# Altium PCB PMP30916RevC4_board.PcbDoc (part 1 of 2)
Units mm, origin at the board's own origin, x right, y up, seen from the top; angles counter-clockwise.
Board outline 58.42 x 31.75 mm, 4 copper layers (Top Layer, Layer 2, Layer 3, Bottom Layer), stack 1.787 mm thick; 61 components, 27 nets, 160 pads, 105 vias.
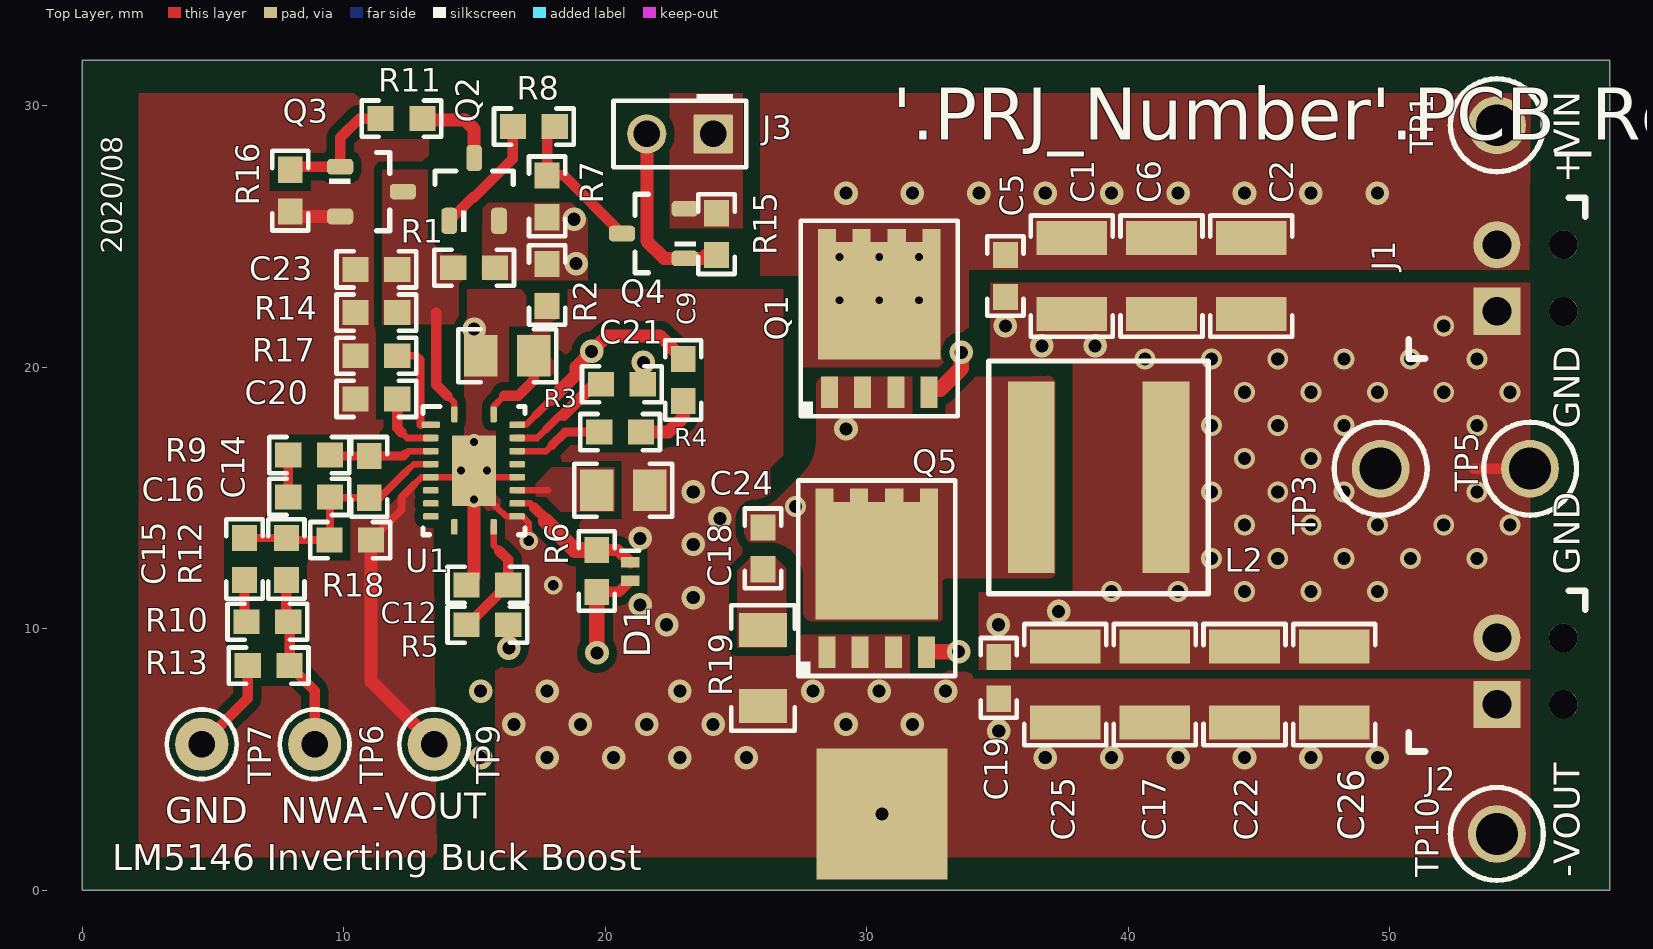
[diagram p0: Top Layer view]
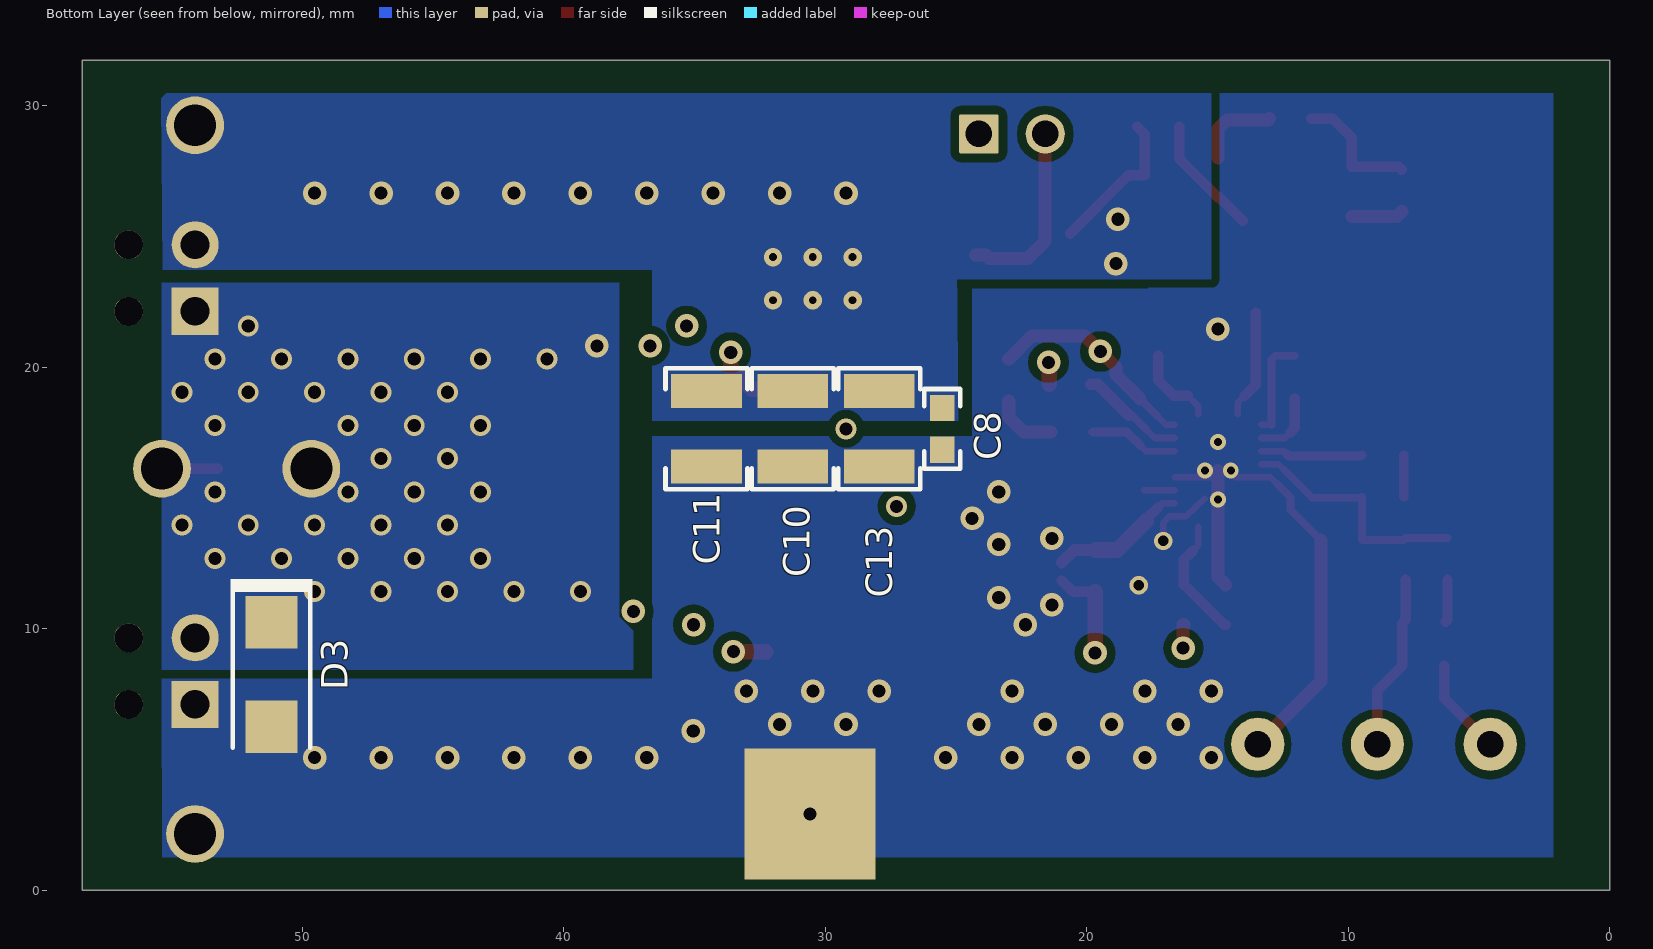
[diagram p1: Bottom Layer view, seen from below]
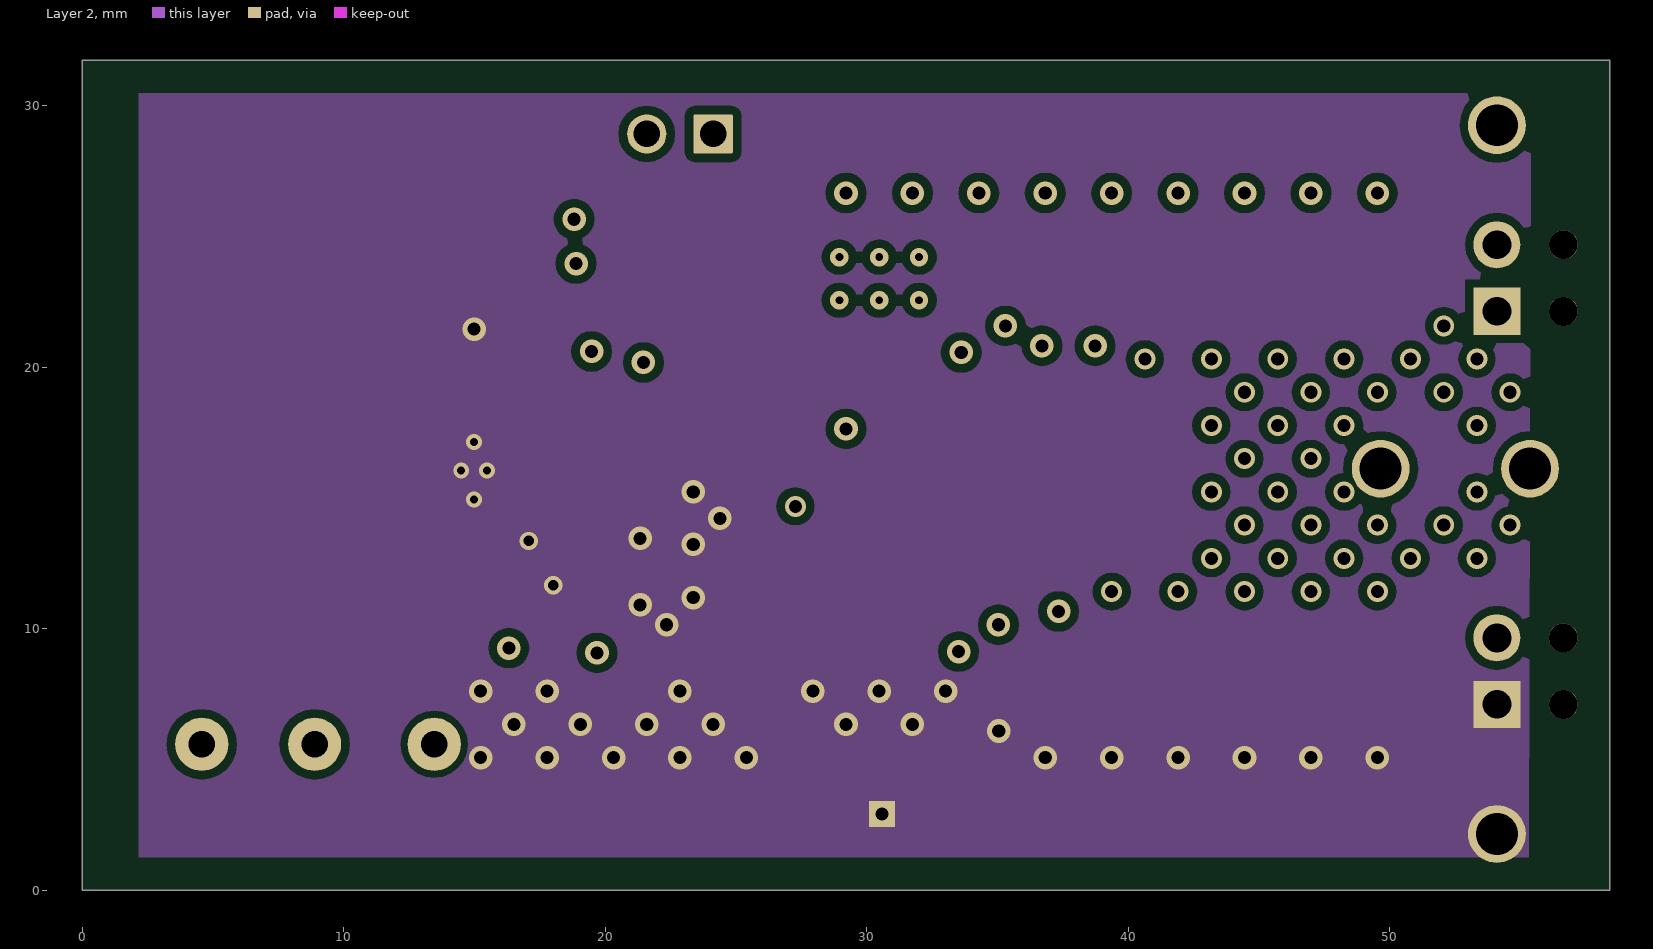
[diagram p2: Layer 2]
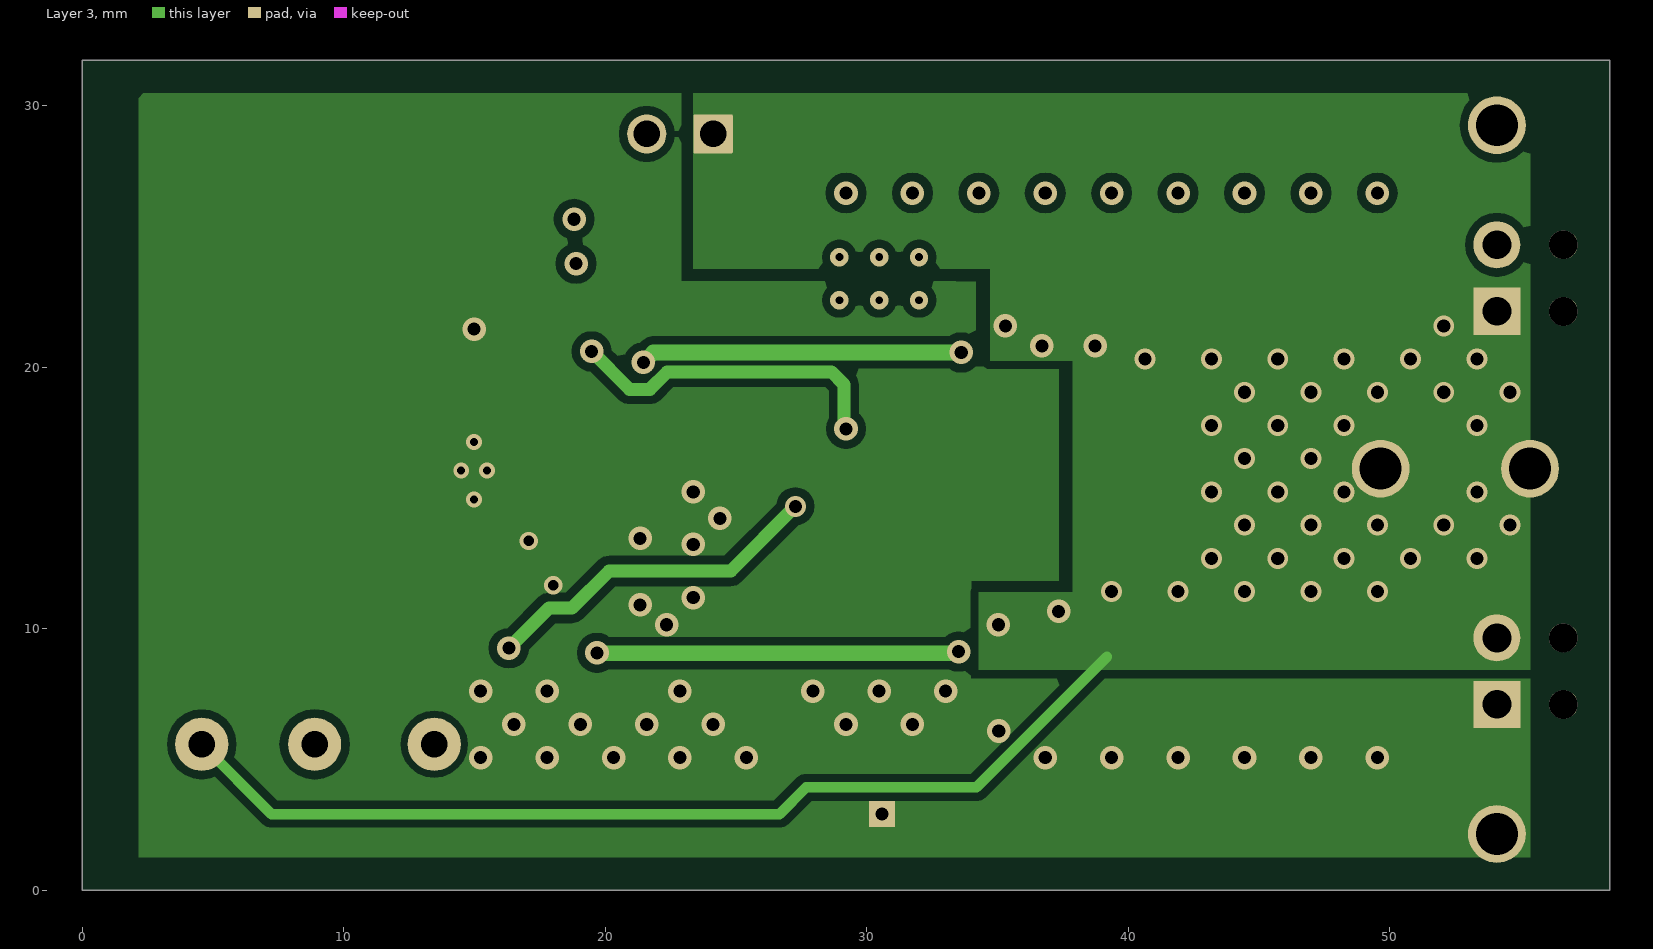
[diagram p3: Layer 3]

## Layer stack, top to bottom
Top Solder: solder mask 0.0102, Solder Resist, Dk 3.5
Top Layer: signal copper 0.0356
Dielectric 1: prepreg 0.0711, PP-006, Dk 4.1
Layer 2: signal copper 0.035
Dielectric1: core 1.5037, FR-4, Dk 4.8
Layer 3: signal copper 0.035
Dielectric 2: prepreg 0.0711, PP-006, Dk 4.1
Bottom Layer: signal copper 0.0356
Bottom Solder: solder mask 0.0102, Solder Resist, Dk 3.5

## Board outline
0,0 0,31.75 58.42,31.75 58.42,0

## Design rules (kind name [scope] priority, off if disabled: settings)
AcuteAngle [All] p1: minimum=4.50000000000000E+0001 checktracksonly=FALSE
AssemblyTestPointUsage [All] p1: valid=2
BoardOutlineClearance BoardOutlineClearance_MountingHoles [OnCopper and InComponentClass('Mounting Holes')] p1: gap=1 ignorepadtopadclearanceinfootprint=FALSE
BoardOutlineClearance BoardOutlineClearance_Poly [OnCopper and IsPoly] p2: gap=0.635 ignorepadtopadclearanceinfootprint=FALSE
BoardOutlineClearance [OnCopper and Not InComponentClass('Logo') and not InComponentClass('FiducialMark') and not InRegion(1000,500,4000,800) and not InPoly] p3: gap=1.905 ignorepadtopadclearanceinfootprint=FALSE
Clearance Clearance_Keepouts [((IsTrack Or IsArc) And Not InPoly) And IsFree and IsKeepOut vs ((IsTrack Or IsArc) And Not InPoly) And IsFree and IsKeepOut] p1: gap=0 ignorepadtopadclearanceinfootprint=FALSE
Clearance clearance_poly-VOUT [InPolygon and InNet('NetC10_2') vs InNet('NetC10_2')] p2: gap=0.2 ignorepadtopadclearanceinfootprint=TRUE
Clearance clearance_poly_VCC [InPolygon and InNet('NetC24_1')] p3: gap=0.2 ignorepadtopadclearanceinfootprint=TRUE
Clearance Clearance_Poly [InPolygon] p4: gap=0.32 ignorepadtopadclearanceinfootprint=TRUE
Clearance Clearance_FiducialMark [IsKeepOut and InComponentClass('FiducialMark') vs IsPad and InComponentClass('FiducialMark')] p5: gap=0 ignorepadtopadclearanceinfootprint=FALSE
Clearance [All] p6: gap=0.2 ignorepadtopadclearanceinfootprint=TRUE
ComponentClearance ComponentClearance_MountingHoles_FiducialMarks [InComponentClass('Mounting Holes') vs InComponentClass('FiducialMark')] p1: gap=1.27 collisioncheckmode=3 verticalgap=0.254 showdistances=FALSE
ComponentClearance ComponentClearance_Shunt [InComponentClass('Header') vs InComponentClass('Shunt')] p2: gap=0 collisioncheckmode=3 verticalgap=0 showdistances=FALSE
ComponentClearance ComponentClearance_Logo [InComponentClass('Logo')] p3: gap=1.27 collisioncheckmode=3 verticalgap=0.254 showdistances=FALSE
ComponentClearance ComponentClearance_ScrewToNut [(HasFootprint('NY PMS 440 0025 PH')) vs (HasFootprint('Keystone_1902C'))] p4: gap=0.127 collisioncheckmode=3 verticalgap=0.254 showdistances=FALSE
ComponentClearance ComponentClearance_MountingHoles [InComponentClass('Mounting Holes')] p5: gap=6.35 collisioncheckmode=3 verticalgap=2540 showdistances=FALSE
ComponentClearance ComponentClearance_SmallPassives [HasFootprint('0201*') or HasFootprint('0402*') or HasFootprint('0508') or HasFootprint('0603*') or HasFootprint('0612') or HasFootprint('0805*') or HasFootprint('0815*') or HasFootprint('0830*') or HasFootprint('1206*') or HasFootprint('1210*') or HasFootprint('1808*') or HasFootprint('1812*') or HasFootprint('1825*') or HasFootprint('2010*') or HasFootprint('2220*') or HasFootprint('2225*') or HasFootprint('2512*') or HasFootprint('2728*') or HasFootprint('3518*') or HasFootprint('X1-DFN1006-2') vs HasFootprint('0201*') or HasFootprint('0402*') or HasFootprint('0508') or HasFootprint('0603*') or HasFootprint('0612') or HasFootprint('0805*') or HasFootprint('0815*') or HasFootprint('0830*') or HasFootprint('1206*') or HasFootprint('1210*') or HasFootprint('1808*') or HasFootprint('1812*') or HasFootprint('1825*') or HasFootprint('2010*') or HasFootprint('2220*') or HasFootprint('2225*') or HasFootprint('2512*') or HasFootprint('2728*') or HasFootprint('3518*') or HasFootprint('X1-DFN1006-2')] p6: gap=0.38 collisioncheckmode=3 verticalgap=0.254 showdistances=FALSE
ComponentClearance ComponentClearance_THtoSMT [IsThruComponent vs IsSMTComponent] p7: gap=1.016 collisioncheckmode=3 verticalgap=0.762 showdistances=FALSE
ComponentClearance ComponentClearance_THtoTH [IsThruComponent vs IsThruComponent] p8: gap=0.762 collisioncheckmode=3 verticalgap=0.762 showdistances=FALSE
ComponentClearance [All] p9: gap=0.762 collisioncheckmode=3 verticalgap=0.254 showdistances=FALSE
DiffPairsRouting [All] p1: maxlimit=2.54 minlimit=0.254 mostfreqgap=0.254 toplayer_minwidth=0.381 toplayer_maxwidth=0.381 toplayer_prefwidth=0.381 midlayer1_minwidth=0.381 midlayer1_maxwidth=0.381 midlayer1_prefwidth=0.381 midlayer2_minwidth=0.381 midlayer2_maxwidth=0.381 midlayer2_prefwidth=0.381 bottomlayer_minwidth=0.381 bottomlayer_maxwidth=0.381 bottomlayer_prefwidth=0.381 maxuncoupledlength=25.4
FabricationTestPointUsage TestPointUsage [All] p1: valid=2 allowmultiple=FALSE
FabricationTestpoint Testpoint [All] p1: side=3 testpointundercomponent=TRUE minsize=1.016 maxsize=2.54 preferedsize=1.524 minholesize=0 maxholesize=1.016 preferedholesize=0.813 testpointgrid=0.025 allowsidetop=TRUE allowsidebottom=TRUE usegrid=TRUE gridtolerance=0
FanoutControl Fanout_LCC [IsLCC] p1: bgadir=Out bgaviamode=Centered fanoutstyle=Auto fanoutdirection=Alternating viagrid=0.025 // Fanout_LCC (Default Rule)
FanoutControl Fanout_BGA [IsBGA] p2: bgadir=Out bgaviamode=Centered fanoutstyle=Auto fanoutdirection=Alternating viagrid=0.025 // Fanout_BGA (Default Rule)
FanoutControl Fanout_Default [All] p4: bgadir=Out bgaviamode=Centered fanoutstyle=Auto fanoutdirection=Alternating viagrid=0.025 // Fanout_Default (Default Rule)
FanoutControl Fanout_Small [(CompPinCount < 5)] p5: bgadir=Out bgaviamode=Centered fanoutstyle=Auto fanoutdirection=OutThenIn viagrid=0.025 // Fanout_Small (Default Rule)
HoleSize [All] p1: absolutevalues=TRUE maxlimit=6.375 minlimit=0.3 maxpercent=80.000 minpercent=20.000
MinimumAnnularRing MinimumAnnularRing_ThermalPadVias [IsVia and InAnyComponent] p1: minimumring=0.15
MinimumAnnularRing [All] p2: minimumring=0.2
MinimumSolderMaskSliver MinimumSolderMaskSliver_Logo [InComponentClass('Logo') vs InComponentClass('Logo')] p1: minsoldermaskwidth=0.018
MinimumSolderMaskSliver [All] p2: minsoldermaskwidth=0.1
PlaneConnect [All] p1: planeconnectstyle=Relief reliefexpansion=0.254 reliefentries=4 reliefconductorwidth=0.254 reliefairgap=0.254
PolygonConnect PolygonConnect_TP9 [All vs InComponent('TP9')] p1: thpad.connectstyle=NoConnect thpad.reliefconductorwidth=0.254 thpad.reliefentries=4 thpad.polygonreliefangle="90 Angle" thpad.airgapwidth=0.254 smdpad.connectstyle=Relief smdpad.reliefconductorwidth=0.254 smdpad.reliefentries=4 smdpad.polygonreliefangle="90 Angle" smdpad.airgapwidth=0.254 via.connectstyle=Relief via.reliefconductorwidth=0.254 via.reliefentries=4 via.polygonreliefangle="90 Angle" via.airgapwidth=0.254
PolygonConnect PolygonConnect_TP7 [All vs InComponent('TP7')] p2: thpad.connectstyle=NoConnect thpad.reliefconductorwidth=0.254 thpad.reliefentries=4 thpad.polygonreliefangle="90 Angle" thpad.airgapwidth=0.254 smdpad.connectstyle=Direct smdpad.reliefconductorwidth=0.254 smdpad.reliefentries=4 smdpad.polygonreliefangle="90 Angle" smdpad.airgapwidth=0.254 via.connectstyle=Direct via.reliefconductorwidth=0.254 via.reliefentries=4 via.polygonreliefangle="90 Angle" via.airgapwidth=0.254
PolygonConnect [All] p3: connectstyle=Direct reliefconductorwidth=0.254 reliefentries=4 polygonreliefangle="90 Angle" airgapwidth=0.254
RoutingVias ThermalPadVias [IsVia and InAnyComponent] p1: holewidth=0.2 width=0.5 viastyle="Through Hole" minholewidth=0.2 minwidth=0.5 maxholewidth=0.33 maxwidth=0.6
RoutingVias [All] p2: holewidth=0.5 width=0.9 viastyle="Through Hole" minholewidth=0.3 minwidth=0.6 maxholewidth=1.016 maxwidth=1.651
SilkToBoardRegionClearance [Not ((IsComment or IsDesignator) And (Hide <> 'False')) and not InRegion(1000,500,4000,800)] p1:
SilkToSilkClearance SilkToSilkClearance_Pb-FreeLogo [(HasFootprint('Pb-Free_Overlay_Medium') OR HasFootprint('Pb-Free_Overlay_Small')) vs (HasFootprint('Pb-Free_Overlay_Medium') OR HasFootprint('Pb-Free_Overlay_Small'))] p1: silktosilkclearance=0
SilkToSilkClearance [All] p2: silktosilkclearance=0.1
SilkToSolderMaskClearance SilkToComponentPadClearance [(IsPad or IsFill or IsRegion) and InAnycomponent] p1: minsilkscreentomaskgap=0.127 clearancetoexposedcopper=TRUE
SilkToSolderMaskClearance "Silk to Solder Mask Opening" [All] p2: minsilkscreentomaskgap=0.1 clearancetoexposedcopper=FALSE
SolderMaskExpansion [All] p1: expansion=0.05 istentingtop=FALSE
UnRoutedNet [All] p1: checkbadconnections=TRUE
Width [All] p1: maxlimit=2.54 minlimit=0.152 preferedwidth=0.254 checkconnectedcopper=TRUE
14 further rules are at their usual default settings.

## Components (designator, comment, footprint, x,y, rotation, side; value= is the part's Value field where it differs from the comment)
C1 "GRM32ER72A225KA35L" 1210_270 37.846,23.495 r270 top value=2.2uF
C2 "GRM32ER72A225KA35L" 1210_270 44.704,23.495 r270 top value=2.2uF
C5 "GRM188R72A104KA35D" 0603 35.306,23.495 r270 top value=0.1uF
C6 "GRM32ER72A225KA35L" 1210_270 41.275,23.495 r270 top value=2.2uF
C8 "GRM188R72A104KA35D" 0603 25.527,17.653 r270 bottom value=0.1uF
C9 "GRM188R71E104KA01D" 0603 22.987,19.52 r90 top value=0.1uF
C10 "GRM32ER72A225KA35L" 1210_270 31.242,17.653 r270 bottom value=2.2uF
C11 "GRM32ER72A225KA35L" 1210_270 34.544,17.653 r270 bottom value=2.2uF
C12 "GRM1885C1H270JA01D" 0603 15.494,11.684 r180 top value=27pF
C13 "GRM32ER72A225KA35L" 1210_270 27.94,17.653 r270 bottom value=2.2uF
C14 "GRM188R71H471KA01D" 0603 10.976,15.815 r270 top value=470pF
C15 "GRM188R71H102KA01D" 0603 6.208,12.676 r90 top value=1000pF
C16 "GRM188R71H103KA01D" 0603 8.683,15.051 r0 top value=0.01uF
C17 "GRM32ER71E226KE15L" 1210_270 41.021,7.874 r90 top value=22uF
C18 "C1608X7R2A102K080AA" 0603 26.035,13.081 r270 top value=1000pF
C19 "GRM188R71E104KA01D" 0603 35.052,8.128 r270 top value=0.1uF
C20 "GRM188R71C683KA01D" 0603 11.246,18.796 r180 top value=0.068uF
C21 "GRM21BR72A474KA73L" 0805_HV 16.256,20.447 r180 top value=0.47uF
C22 "GRM32ER71E226KE15L" 1210_270 44.45,7.874 r90 top value=22uF
C23 "GRM1885C1H101JA01D" 0603 11.246,23.749 r180 top value=100pF
C24 "GCM21BR71E225KA73L" 0805_HV 20.691,15.306 r0 top value=2.2uF
C25 "GRM32ER71E226KE15L" 1210_270 37.592,7.874 r90 top value=22uF
C26 "GRM32ER71E226KE15L" 1210_270 47.879,7.874 r90 top value=22uF
D1 "BAT54LP-7" X1-DFN1006-2 20.955,12.192 r270 top value=30V
D3 "B2100A-13-F" SMA 51.181,8.255 r270 bottom value=100V
J1 "1725656" CONN_1725656 54.102,23.419 r90 top
J2 "1725656" CONN_1725656 54.102,8.387 r90 top
J3 "PEC02SAAN" CONN_PEC02SAAN 22.86,28.93 r180 top
L2 "XAL8080-223MEB" XAL8080 38.867,15.799 r0 top value=22uH
Q1 "BSC117N08NS5ATMA1" PG-TDSON-8 30.48,21.875 r90 top value=80V
Q2 "BSS63" SOT-23 14.989,26.807 r90 top value="100 V"
Q3 "BSS123" SOT-23 11.066,26.725 r0 top value=100V
Q4 "BSS123" SOT-23 21.844,25.12 r180 top value=100V
Q5 "BSC117N08NS5ATMA1" PG-TDSON-8 30.385,11.938 r90 top value=80V
R1 "CRCW0603200KFKEA" 0603 14.989,23.81 r0 top value=200k
R2 "RMCF0603ZT0R00" 0603 17.78,23.152 r90 top value=0
R3 "CRCW06034R75FKEA" 0603 20.636,19.357 r0 top value=4.75
R4 "RMCF0603ZT0R00" 0603 20.574,17.526 r0 top value=0
R5 "CRCW0603215RFKEA" 0603 15.494,10.16 r0 top value=215
R6 "RMCF0603ZT0R00" 0603 19.675,12.216 r270 top value=0
R7 "CRCW0603100KFKEA" 0603 17.78,26.543 r270 top value=100k
R8 "CRCW060349K9FKEA" 0603 17.272,29.21 r180 top value=49.9k
R9 "CRCW06034K99FKEA" 0603 8.683,16.648 r0 top value=4.99k
R10 "CRCW06032K67FKEA" 0603 7.083,10.273 r0 top value=2.67k
R11 "CRCW0603100KFKEA" 0603 12.209,29.519 r0 top value=100k
R12 "CRCW060349K9FKEA" 0603 7.808,12.676 r270 top value=49.9k
R13 "RC0603FR-0749R9L" 0603 7.133,8.598 r180 top value=49.9
R14 "CRCW060335K7FKEA" 0603 11.246,22.098 r0 top value=35.7k
R15 "CRCW060320K0FKEA" 0603 24.257,25.096 r270 top value=20.0k
R16 "CRCW060320K0FKEA" 0603 7.958,26.758 r90 top value=20.0k
R17 "CRCW060324K9FKEA" 0603 11.246,20.447 r0 top value=24.9k
R18 "CRCW06035K49FKEA" 0603 10.251,13.401 r180 top value=5.49k
R19 "CRCW120610R0JNEA" 1206 26.035,8.509 r90 top value=10
TP1 "5010" Keystone5010 54.102,29.261 r90 top
TP3 "5011" Keystone5011 49.657,16.129 r90 top
TP5 "5011" Keystone5011 55.372,16.129 r90 top
TP6 "5003" Keystone5003 8.89,5.588 r90 top
TP7 "5001" Keystone5001 4.572,5.588 r90 top
TP9 "5117" Keystone5117 13.462,5.588 r90 top value=Blue
TP10 "5127" Keystone5127 54.102,2.159 r90 top
U1 "LM5146QRGYRQ1" RGY0020B 14.984,16.052 r0 top

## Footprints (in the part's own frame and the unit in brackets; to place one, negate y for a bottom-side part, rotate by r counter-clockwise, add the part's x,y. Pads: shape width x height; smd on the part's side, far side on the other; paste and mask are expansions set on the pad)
0603 [mm] "0603 from SM-752 data"
  rect 1x0.95 smd: 1(-0.8,0) 2(0.8,0)
  silkscreen extent -1.52,-0.69 1.52,0.69, body extent -0.87,-0.47 0.87,0.47, height 1
0805_HV [mil] "0805 with 30mil clearance between pads"
  rect 50x63 smd: 1(-40,0) 2(40,0)
  silkscreen extent -74,-40 74,40, body extent -43,-29 43,29, height 57
1206 [mm] "1206 from SM-752 data"
  rect 1.3x1.85 smd: 1(-1.45,0) 2(1.45,0)
  silkscreen extent -2.4,-1.21 2.4,1.21, body extent -1.7,-0.9 1.7,0.9, height 1.35
1210_270 [mm] "1210"
  rect 1.3x2.7 smd: 1(-1.45,0) 2(1.45,0)
  silkscreen extent -2.32,-1.57 2.32,1.57, body extent -1.7,-1.35 1.7,1.35, height 2.7
CONN_1725656 [mm] "Phoenix Contact"
  rect 1.8x1.8 hole 1.1: 1(-1.27,0)
  round 1.8 hole 1.1: 2(1.27,0)
  round 1.1 hole 1.1 unplated: MH1(-1.275,-2.54) MH2(1.27,-2.54)
  silkscreen extent -3.08,-3.37 3.08,3.37, body extent -2.77,-3.1 2.77,3.1, height 8.52
CONN_PEC02SAAN [mm] "SULLINS"
  rrect7% 1.5x1.5 hole 1.016: 1(-1.27,0)
  round 1.5 hole 1.016: 2(1.27,0)
  silkscreen extent -2.54,-1.52 2.54,1.27, body extent -2.54,-1.27 2.54,1.27, height 8.38
Keystone5001 [mil] "For Keystone 500x miniature loop terminals"
  round 80 hole 40: 1(0,0)
  silkscreen extent -52,-52 52,52, body extent -49,-49 49,49, height 182
Keystone5003 [mil] "For Keystone 500x miniature loop terminals"
  round 80 hole 40: 1(0,0)
  silkscreen extent -52,-52 52,52, body extent -49,-49 49,49, height 182
Keystone5010 [mil] "Keystone Multipurpose loops"
  round 87 hole 63: 1(0,0)
  silkscreen extent -70,-70 70,70, body extent -63,-63 63,62, height 319
Keystone5011 [mil] "Keystone Multipurpose loops"
  round 87 hole 63: 1(0,0)
  silkscreen extent -70,-70 70,70, body extent -63,-63 63,62, height 319
Keystone5117 [mil] "For Keystone 500x miniature loop terminals"
  round 80 hole 40: 1(0,0)
  silkscreen extent -52,-52 52,52, body extent -49,-49 49,49, height 182
Keystone5127 [mil] "Keystone Multipurpose loops"
  round 87 hole 63: 1(0,0)
  silkscreen extent -70,-70 70,70, body extent -63,-63 63,62, height 319
PG-TDSON-8 [mm] "Infineon recommended land pattern"
  rect 1.2x0.65 smd: 1(-2.825,1.905) 2(-2.825,0.635) 3(-2.825,-0.635) 4(-2.825,-1.905)
  rect 0.5x0.7 smd: 5(3.175,-2) 6(3.175,-0.675) 7(3.175,0.675) 8(3.175,2)
  rect 4.5x4.7 smd paste-2.25: 9(0.675,0)
  silkscreen extent -3.74,-3 3.74,3, body extent -3.17,-2.89 3.17,2.9, height 1.1
RGY0020B [mm] "QFN, 20-Leads, Body 4.5x3.5mm, Pitch 0.5mm, Thermal Pad 2.7x1.7mm"
  rrect40% 0.25x0.6 smd: 1(-0.75,2.15) 10(-0.75,-2.15) 11(0.75,-2.15) 20(0.75,2.15)
  rrect40% 0.7x0.25 smd: 2(-1.65,1.75)
  rrect40% 0.6x0.25 smd: 3(-1.65,1.25) 4(-1.65,0.75) 5(-1.65,0.25) 6(-1.65,-0.25) 7(-1.65,-0.75) 8(-1.65,-1.25) 9(-1.65,-1.75) 12(1.65,-1.75) 13(1.65,-1.25) 14(1.65,-0.75) 15(1.65,-0.25) 16(1.65,0.25) 17(1.65,0.75) 18(1.65,1.25) 19(1.65,1.75)
  rrect13% 0.75x1.21 on Top Paste: 21(-0.475,-0.705) 21(-0.475,0.705) 21(0.475,-0.705) 21(0.475,0.705)
  rrect6% 1.7x2.7 smd paste-1.4: 21(0,0)
  silkscreen extent -1.95,-2.45 1.95,2.45, body extent -1.75,-2.25 1.75,2.25, height 0.9
SMA [mm] "Molded Diode, 2-Leads, Body 4.3x2.6mm, IPC Medium Density, based on OnSemi component dimensions and land pattern"
  rect 2x2 smd: 1(-2,0) 2(2,0)
  silkscreen extent -3.66,-1.57 2.79,1.57, body extent -2.6,-1.3 2.6,1.3, height 2.42
SOT-23 [mm] "SOT23, 3-Leads, Body 2.9x1.3mm, Pitch 0.95mm, Lead Span 2.5mm, IPC Medium Density"
  rrect50% 1x0.6 smd: 1(-1.2,0.95) 2(-1.2,-0.95) 3(1.2,0)
  silkscreen extent -1.62,-1.5 0.7,1.5, body extent -1.16,-1.45 1.21,1.45, height 1
X1-DFN1006-2 [mm] "DIODES, INC"
  rect 0.4x0.7 smd: 1(-0.35,0) 2(0.35,0)
  silkscreen extent -0.8,-0.35 -0.8,0.35, body extent -0.54,-0.34 0.54,0.34, height 0.53
XAL8080 [mm] "Coilcraft"
  rect 1.78x7.31 smd: 1(-2.58,0) 2(2.58,0)
  silkscreen extent -4.2,-4.45 4.2,4.45, body extent -4.15,-4.4 4.15,4.4, height 8

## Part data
C1 C2 C6 C10 C11 C13: "CAP, CERM, 2.2 µF, 100 V,+/- 10%, X7R, 1210", Cap_Case=1210, Manufacturer=MuRata, Supplier Part Number 1=490-3385-1-ND, TempCo=X7R, Tolerance_%=10, Value1="0.007 ohm", Value2=100V, ValueDisplayed=2.2µF
C5 C8: "CAP, CERM, 0.1 µF, 100 V,+/- 10%, X7R, 0603", Cap_Case=0603, Manufacturer=MuRata, Supplier Part Number 1=490-3285-1-ND, TempCo=X7R, Tolerance_%=10, Value2=100V, ValueDisplayed=0.1µF
C9 C19: "CAP, CERM, 0.1 µF, 25 V,+/- 10%, X7R, 0603", Cap_Case=0603, Manufacturer=MuRata, Supplier Part Number 1=490-1524-1-ND, TempCo=X7R, Tolerance_%=10, Value2=25V, ValueDisplayed=0.1µF
C12: "CAP, CERM, 27 pF, 50 V,+/- 5%, C0G/NP0, 0603", Cap_Case=0603, Manufacturer=MuRata, Supplier Part Number 1=490-1413-1-ND, TempCo=C0G/NP0, Tolerance_%=5, Value2=50V, ValueDisplayed=27pF
C14: "CAP, CERM, 470 pF, 50 V,+/- 10%, X7R, 0603", Cap_Case=0603, Manufacturer=MuRata, Supplier Part Number 1=490-1489-1-ND, TempCo=X7R, Tolerance_%=10, Value2=50V, ValueDisplayed=470pF
C15: library part CMP-0007432-5, "CAP, CERM, 1000 pF, 50 V, +/- 10%, X7R, 0603", Cap_Case=0603, Manufacturer=MuRata, Supplier Part Number 1=490-1494-1-ND, TempCo=X7R, Tolerance_%=10%, Value1=Unknown, Value2=50V, ValueDisplayed=1000pF
C16: library part CMP-0007433-4, "CAP, CERM, 0.01 uF, 50 V, +/- 10%, X7R, 0603", Cap_Case=0603, Manufacturer=MuRata, Supplier Part Number 1=490-1512-1-ND, TempCo=X7R, Tolerance_%=10%, Value1=Unknown, Value2=50V, ValueDisplayed=0.01uF
C17 C22 C25 C26: "CAP, CERM, 22 µF, 25 V,+/- 10%, X7R, 1210", Cap_Case=1210, Manufacturer=MuRata, Supplier Part Number 1=490-5313-1-ND, TempCo=X7R, Tolerance_%=10, Value1="0.002334 ohm", Value2=25V, ValueDisplayed=22µF
C18: library part CMP-0007053-4, "CAP, CERM, 1000 pF, 100 V, +/- 10%, X7R, 0603", Cap_Case=0603, Manufacturer=TDK, Supplier Part Number 1=445-1298-1-ND, TempCo=X7R, Tolerance_%=10%, Value1=Unknown, Value2=100V, ValueDisplayed=1000pF
C20: library part CMP-0007400-1, "CAP, CERM, 0.068 uF, 16 V, +/- 10%, X7R, 0603", Cap_Case=0603, Manufacturer=MuRata, Supplier Part Number 1=490-1531-1-ND, TempCo=X7R, Tolerance_%=10%, Value1=Unknown, Value2=16V, ValueDisplayed=68nF
C21: library part CMP-0008374-2, "CAP, CERM, 0.47 uF, 100 V, +/- 10%, X7R, 0805", Cap_Case=0805, Manufacturer=MuRata, Supplier Part Number 1=490-3326-1-ND, TempCo=X7R, Tolerance_%=10%, Value1=Unknown, Value2=100V, ValueDisplayed=0.47uF
C23: "CAP, CERM, 100 pF, 50 V,+/- 5%, C0G/NP0, 0603", Cap_Case=0603, Manufacturer=MuRata, Supplier Part Number 1=490-1427-1-ND, TempCo=C0G/NP0, Tolerance_%=5, Value2=50V, ValueDisplayed=100pF
C24: library part CMP-0083622-1, "CAP, CERM, 2.2 µF, 25 V,+/- 10%, X7R, AEC-Q200 Grade 1, 0805", Cap_Case=0805, Manufacturer=MuRata, Supplier Part Number 1=490-4787-1-ND, TempCo=X7R, Tolerance_%=10%, Value2=25V, ValueDisplayed=2.2µF
D1: library part CMP-0076931-2, "Diode, Schottky, 30 V, 0.2 A, 1.00x0.50x0.60mm", Manufacturer="Diodes Inc.", Value1=0.2A, Value2=1V
D3: library part CMP-0081099-2, "Diode, Schottky, 100 V, 2 A, SMA", Manufacturer="Diodes Inc.", Value1=2A, Value2=0.79V
J1 J2: library part CMP-0055479-2, "Terminal Block, 100mil, 2x1, 6A, 63V, TH", Manufacturer="Phoenix Contact", Supplier Part Number 1=71C4107
J3: "Header, 100mil, 2x1, Tin, TH", Color=Black, Current_A=3, Manufacturer="Sullins Connector Solutions", Supplier Part Number 1=S1012E-02-ND, Voltage_V=1800
L2: library part XAL8080-103MEB, "Inductor, Shielded, Composite, 22 µH, 5.9 A, 0.033 ohm, SMD", Manufacturer=Coilcraft, Supplier Part Number 1=994-XAL8080-223MEB, Value1="0.033 ohm", Value2=5.9A, ValueDisplayed=22µH
Q1 Q5: "MOSFET, N-CH, 80 V, 49 A, PG-TDSON-8", Alternate Manufacturer=None, Manufacturer="Infineon Technologies", Supplier Part Number 1=BSC117N08NS5ATMA1-ND, Value1="? ohm", Value2="15 nC"
Q2: library part "BSS63, Fairchild Semiconductor", "Transistor, PNP, 100 V, 0.2 A, SOT-23", Manufacturer="Fairchild Semiconductor", Supplier Part Number 1=BSS63CT-ND, Value1="0.2 A"
Q3 Q4: "MOSFET, N-CH, 100 V, 0.17 A, SOT-23", Alternate Manufacturer=None, Manufacturer="Fairchild Semiconductor", Supplier Part Number 1=BSS123NCT-ND, Value1="10 ohm", Value2="1.8 nC"
R1: "RES, 200 k, 1%, 0.1 W, 0603", Manufacturer=Vishay-Dale, Power_W=0.1, Supplier Part Number 1=541-200KHCT-ND, TempCo="100 ppm/C", Tolerance_%=1, Value1=1%, Value2=0.1W, Value_Code=200k
R2 R4 R6: library part CMP-0023343-1, "RES, 0, 1%, 0.1 W, AEC-Q200 Grade 0, 0603", Manufacturer="Stackpole Electronics Inc", Power_W=100mW, Supplier Part Number 1=RMCF0603ZT0R00CT-ND, TempCo=ppm/C, Tolerance_%=1%, Value2=0.1W, Value_Code=0
R3: library part CMP-0022476-4, "RES, 4.75, 1%, 0.1 W, AEC-Q200 Grade 0, 0603", Manufacturer=Vishay-Dale, Power_W=100mW, Supplier Part Number 1=541-4.75HHCT-ND, TempCo="100 ppm/C", Tolerance_%=1%, Value2=0.1W, Value_Code=4R75, ValueDisplayed=4.75
R5: "RES, 215, 1%, 0.1 W, 0603", Manufacturer=Vishay-Dale, Power_W=0.1, Supplier Part Number 1=541-215HCT-ND, TempCo="100 ppm/C", Tolerance_%=1, Value1=1%, Value2=0.1W, Value_Code=215R, ValueDisplayed=215
R7 R11: "RES, 100 k, 1%, 0.1 W, 0603", Manufacturer=Vishay-Dale, Power_W=0.1, Supplier Part Number 1=541-100KHCT-ND, TempCo="100 ppm/C", Tolerance_%=1, Value1=1%, Value2=0.1W, Value_Code=100k
R8 R12: "RES, 49.9 k, 1%, 0.1 W, 0603", Manufacturer=Vishay-Dale, Power_W=0.1, Supplier Part Number 1=541-49.9KHCT-ND, TempCo="100 ppm/C", Tolerance_%=1, Value1=1%, Value2=0.1W, Value_Code=49k9, ValueDisplayed=49.9k
R9: "RES, 4.99 k, 1%, 0.1 W, 0603", Manufacturer=Vishay-Dale, Power_W=0.1, Supplier Part Number 1=541-4.99KHCT-ND, TempCo="100 ppm/C", Tolerance_%=1, Value1=1%, Value2=0.1W, Value_Code=4k99, ValueDisplayed=4.99k
R10: library part CMP-0022280-4, "RES, 2.67 k, 1%, 0.1 W, AEC-Q200 Grade 0, 0603", Manufacturer=Vishay-Dale, Power_W=100mW, Supplier Part Number 1=541-2.67KHCT-ND, TempCo="100 ppm/C", Tolerance_%=1%, Value2=0.1W, Value_Code=2k67, ValueDisplayed=2.67k
R13: library part CMP-0023143-5, "RES, 49.9, 1%, 0.1 W, 0603", Manufacturer=Yageo, Power_W=100mW, Supplier Part Number 1=311-49.9HRCT-ND, TempCo="100 ppm/C", Tolerance_%=1%, Value2=0.1W, Value_Code=49R9, ValueDisplayed=49.9
R14: "RES, 35.7 k, 1%, 0.1 W, 0603", Manufacturer=Vishay-Dale, Power_W=0.1, Supplier Part Number 1=541-35.7KHCT-ND, TempCo="100 ppm/C", Tolerance_%=1, Value1=1%, Value2=0.1W, Value_Code=35k7, ValueDisplayed=35.7k
R15 R16: "RES, 20.0 k, 1%, 0.1 W, 0603", Manufacturer=Vishay-Dale, Power_W=0.1, Supplier Part Number 1=541-20.0KHCT-ND, TempCo="100 ppm/C", Tolerance_%=1, Value1=1%, Value2=0.1W, Value_Code=20k0, ValueDisplayed=20.0k
R17: "RES, 24.9 k, 1%, 0.1 W, 0603", Manufacturer=Vishay-Dale, Power_W=0.1, Supplier Part Number 1=541-24.9KHCT-ND, TempCo="100 ppm/C", Tolerance_%=1, Value1=1%, Value2=0.1W, Value_Code=24k9, ValueDisplayed=24.9k
R18: "RES, 5.49 k, 1%, 0.1 W, 0603", Manufacturer=Vishay-Dale, Power_W=0.1, Supplier Part Number 1=541-5.49KHCT-ND, TempCo="100 ppm/C", Tolerance_%=1, Value1=1%, Value2=0.1W, Value_Code=5k49, ValueDisplayed=5.49k
R19: "RES, 10, 5%, 0.25 W, 1206", Manufacturer=Vishay-Dale, Power_W=0.25, Supplier Part Number 1=541-10ECT-ND, TempCo="200 ppm/C", Tolerance_%=5, Value1=5%, Value2=0.25W, Value_Code=10R0, ValueDisplayed=10
TP1: library part CMP-0055147-1, "Test Point, Multipurpose, Red, TH", Color=Red, Manufacturer=Keystone, Supplier Part Number 1=36-5010-ND
TP3 TP5: library part CMP-0055148-1, "Test Point, Multipurpose, Black, TH", Color=Black, Manufacturer=Keystone, Supplier Part Number 1=36-5011-ND
TP6: library part CMP-0055140-1, "Test Point, Miniature, Orange, TH", Color=Orange, Manufacturer=Keystone, Supplier Part Number 1=36-5003-ND
TP7: library part CMP-0055138-1, "Test Point, Miniature, Black, TH", Color=Black, Manufacturer=Keystone, Supplier Part Number 1=36-5001-ND
TP9: "Test Point, Miniature, Blue, TH", Color=Blue, Manufacturer=Keystone, Supplier Part Number 1=36-5117-ND
TP10: library part CMP-0055156-1, "Test Point, Multipurpose, Blue, TH", Color=Blue, Manufacturer=Keystone, Supplier Part Number 1=36-5127-ND
U1: library part CMP-0081848-1, "5.5-V to 100-V Synchronous Buck Controller With Wide Duty Cycle Range, RGY0020B (VQFN-20)", Alternate Manufacturer="Texas Instruments", Alternate PartNumber=LM5146QRGYTQ1

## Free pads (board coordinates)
  rect 5x5 / inner rect 1x1 / far side rect 5x5 hole 0.5: 12(30.59,2.921)

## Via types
v1: diameter 0.9, hole 0.5, Top Layer to Bottom Layer, 35 vias
v2: diameter 0.8, hole 0.5, Top Layer to Bottom Layer, 31 vias
v3: diameter 0.9, hole 0.5, Top Layer to Bottom Layer, tented top, 18 vias
v4: diameter 0.8, hole 0.5, Top Layer to Bottom Layer, tented top, 7 vias
v5: diameter 0.7, hole 0.3, Top Layer to Bottom Layer, 6 vias
v6: diameter 0.6, hole 0.3, Top Layer to Bottom Layer, 4 vias
v7: diameter 0.7, hole 0.4, Top Layer to Bottom Layer, tented top, 2 vias
v8: diameter 0.9/0.9/0.9/0.8 (per signal layer), hole 0.5, Top Layer to Bottom Layer, tented bottom, 1 vias
v9: diameter 0.9, hole 0.5, Top Layer to Bottom Layer, tented both sides, 1 vias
